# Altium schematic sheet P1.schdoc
size 297 x 209 mm; Symbol: Drawing-Symbol_A4; @Project Name: Clicky_2026-07-28_14-10-20; @Page Count: 1; @Update Date: 2026-07-28; @Create Date: 2026-07-28; @Schematic Name: Schematic1; @Page No: 1; @Page Name: P1; Company: EasyEDA.com; Version: V1.0; Page Size: A4; Device: Drawing-Symbol_A4; @Create Time: 14:10:52; @Update Time: 14:10:52; Border: 1; Width: 1170; Height: 825; Region Start: 1; X Region Count: 6; Y Region Count: 4; Blade Width: 10; Title Block Position: 3; @Board Name: Board1
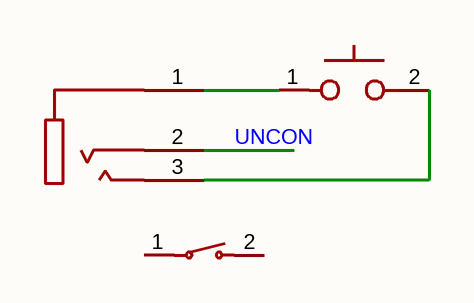
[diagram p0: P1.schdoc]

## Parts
CN1  PJ-320B  [AUDIO-SMD_PJ-320B]  (value not drawn)
U1  CPG151101S11-16  [SMD_KEYBOARD-SW]  (value not drawn)
U2  CPG151101D13  [KEY-TH_CPG151101D21X]  (value not drawn)

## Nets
UNCON: CN1.2
NetCN1_1: CN1.1 U1.1
NetCN1_3: CN1.3 U1.2

Not connected (* = marked no-connect by the designer): U2 1 2

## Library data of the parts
CN1 = PJ-320B_C22355831: Connector Type:3.5mm Headphone Jack Current Rating:25mA Voltage Rating (Max):24V Contact Material:Phosphor Bronze Contact Plating:- Operating Temperature:-25℃~+75℃ Operating Temperature:-25℃~+75℃; Manufacturer: SOFNG(硕方); AddInBom: yes; ModelId: 6785416ebf174739a13857ee45daa8490819f05c4eef4c71ace90d822a990e87; ModelName: AUDIO-PJ320B_L14.0-W6.4-H4.0; ModelTransform: 354.33,551.18,0,0,0,0,0,62.992,-19.685; Current Rating: 25mA; Voltage Rating (Max): 24V
U1 = CPG151101S11-16_C41430893: Manufacturer: HanElectricity(瀚源); AddInBom: yes; ModelId: 3d765b10aea94035884305b41eb862470819f05c4eef4c71ace90d822a990e87; ModelTransform: 582.676,231.8893,0,0,0,0,0,0,-47.244
U2 = CPG151101D13: Axis Type:Blue Switch Operation Force:50gf Conduction Travel:2.2mm Voltage Rating:12V Operating Temperature:-40℃~+70℃ Operating Temperature:-40℃~+70℃; Manufacturer: HanElectricity(瀚源); Add into BOM: yes; ModelId: 22105fb3b67d4e778b6cbc994b8f7b7e0819f05c4eef4c71ace90d822a990e87; ModelName: KEY-TH_L15.6-W14.0-H15.3; ModelTransform: 614.172,551.18,0,90,0,0,25,-150,-137.795; Operation Force: 50gf; Conduction Travel: 2.2mm; Voltage Rating: 12V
